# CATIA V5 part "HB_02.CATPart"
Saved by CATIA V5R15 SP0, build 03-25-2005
Part number: HB_02
Material "Dull Blue": density 7860 kg/m3, Young's modulus 2e+11 Pa, Poisson ratio 0.266
Bounding box of the stored display mesh (mm): x -79 to 0, y 0 to 158, z 0 to 113.2
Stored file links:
  E:\#01 CATIA Lecture Materials\#06 DMU\#11 DMU Page01 KIN EX11\HB_02.CATPart
  E:\공학과제\HB-16.CATPart
  C:\Program Files\Dassault Systemes\B20\win_b64\startup\materials\Catalog.CATMaterial
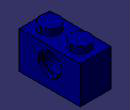
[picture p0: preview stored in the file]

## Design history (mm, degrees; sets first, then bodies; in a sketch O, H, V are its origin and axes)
Body1 (main body), material "Dull Blue"
  Sketch1 on xy-plane, origin (0, 0, 0), H (1, 0, 0), V (0, 1, 0)
    circle A1 centre (-39.5, 39.5) radius 24.5
    point P1 (-39.5, 39.5)
    reference projected line E1 (0, 0) -> (0, 1264)
    reference projected line E2 (-79, 0) -> (-79, 1264)
    reference projected line E3 (-79, 0) -> (0, 0)
    radius A1 = 24.5
    distance P1 E3 = 39.5
    equidistance: E1 E2 P1
  Pad1: profile Sketch1, direction (0, 0, 1), length 113.2
  RectPattern1: of the body so far, direction 1 instances 2, spacing 79, along yz-plane
  Sketch2 on zx-plane, origin (0, 0, 0), H (-1, 0, 0), V (0, 0, 1)
    point P1 (0, 96)
    line L1 (0, 96) -> (79, 96)
    line L2 (79, 96) -> (79, 0)
    line L3 (79, 0) -> (0, 0)
    line L4 (0, 0) -> (0, 96)
    point P3 (79, 0)
    distance L2 L4 = 79
    length L2 = 96
    coincidence: P1 V, P3 H
    horizontal: L1 H, L3 H
    vertical: L2 V, L4 V
  Pad2: profile Sketch2, direction (0, 1, 0), length 158 {= RectPattern1.Nb1 * (79*1mm)}
  Plane1: type Offset, RefPlane zx-plane, Offset 79
  Sketch3 on Plane1, origin (0, 79, 0), H (-1, 0, 0), V (0, 0, 1)
    axis line L1 (95.3003, 56) -> (-23.8651, 56)
    reference projected line E1 (79, 96) -> (0, 96) from edge [start face of Pad2 | face of Pad2 from Sketch2.L1]
    point P3 (79, 56)
    line L2 (79, 56) -> (79, 85.25)
    line L3 (79, 85.25) -> (69, 85.25)
    line L4 (69, 85.25) -> (69, 80.25)
    line L5 (69, 80.25) -> (10, 80.25)
    line L6 (10, 80.25) -> (10, 85.25)
    point P8 (10, 85.25)
    line L7 (10, 85.25) -> (0, 85.25)
    point P9 (0, 85.25)
    line L8 (0, 85.25) -> (0, 56)
    point P10 (0, 56)
    reference projected line E2 (79, 0) -> (79, 96) from edge [start face of Pad2 | face of Pad2 from Sketch2.L2]
    distance L1 E1 = 40
    distance L8 L6 = 10
    distance L4 L2 = 10
    distance L5 L1 = 24.25
    distance L7 L1 = 29.25
    horizontal: L1 H, L3 H, L5 H, L7 H
    coincidence: P3 L1, P8 L3, P9 V, P10 L1, L2 E2
    vertical: L2 V, L4 V, L6 V, L8 V
  Groove1: profile Sketch3, axis Sketch3.L1, angle 360
  Shell1: ExtOffset 0, Face face of Pad2, IntOffset 10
